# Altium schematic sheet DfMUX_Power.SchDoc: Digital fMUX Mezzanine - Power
size 513 x 386 mm; Engineer: M.Dobbs, McGill U.; Revision: 4
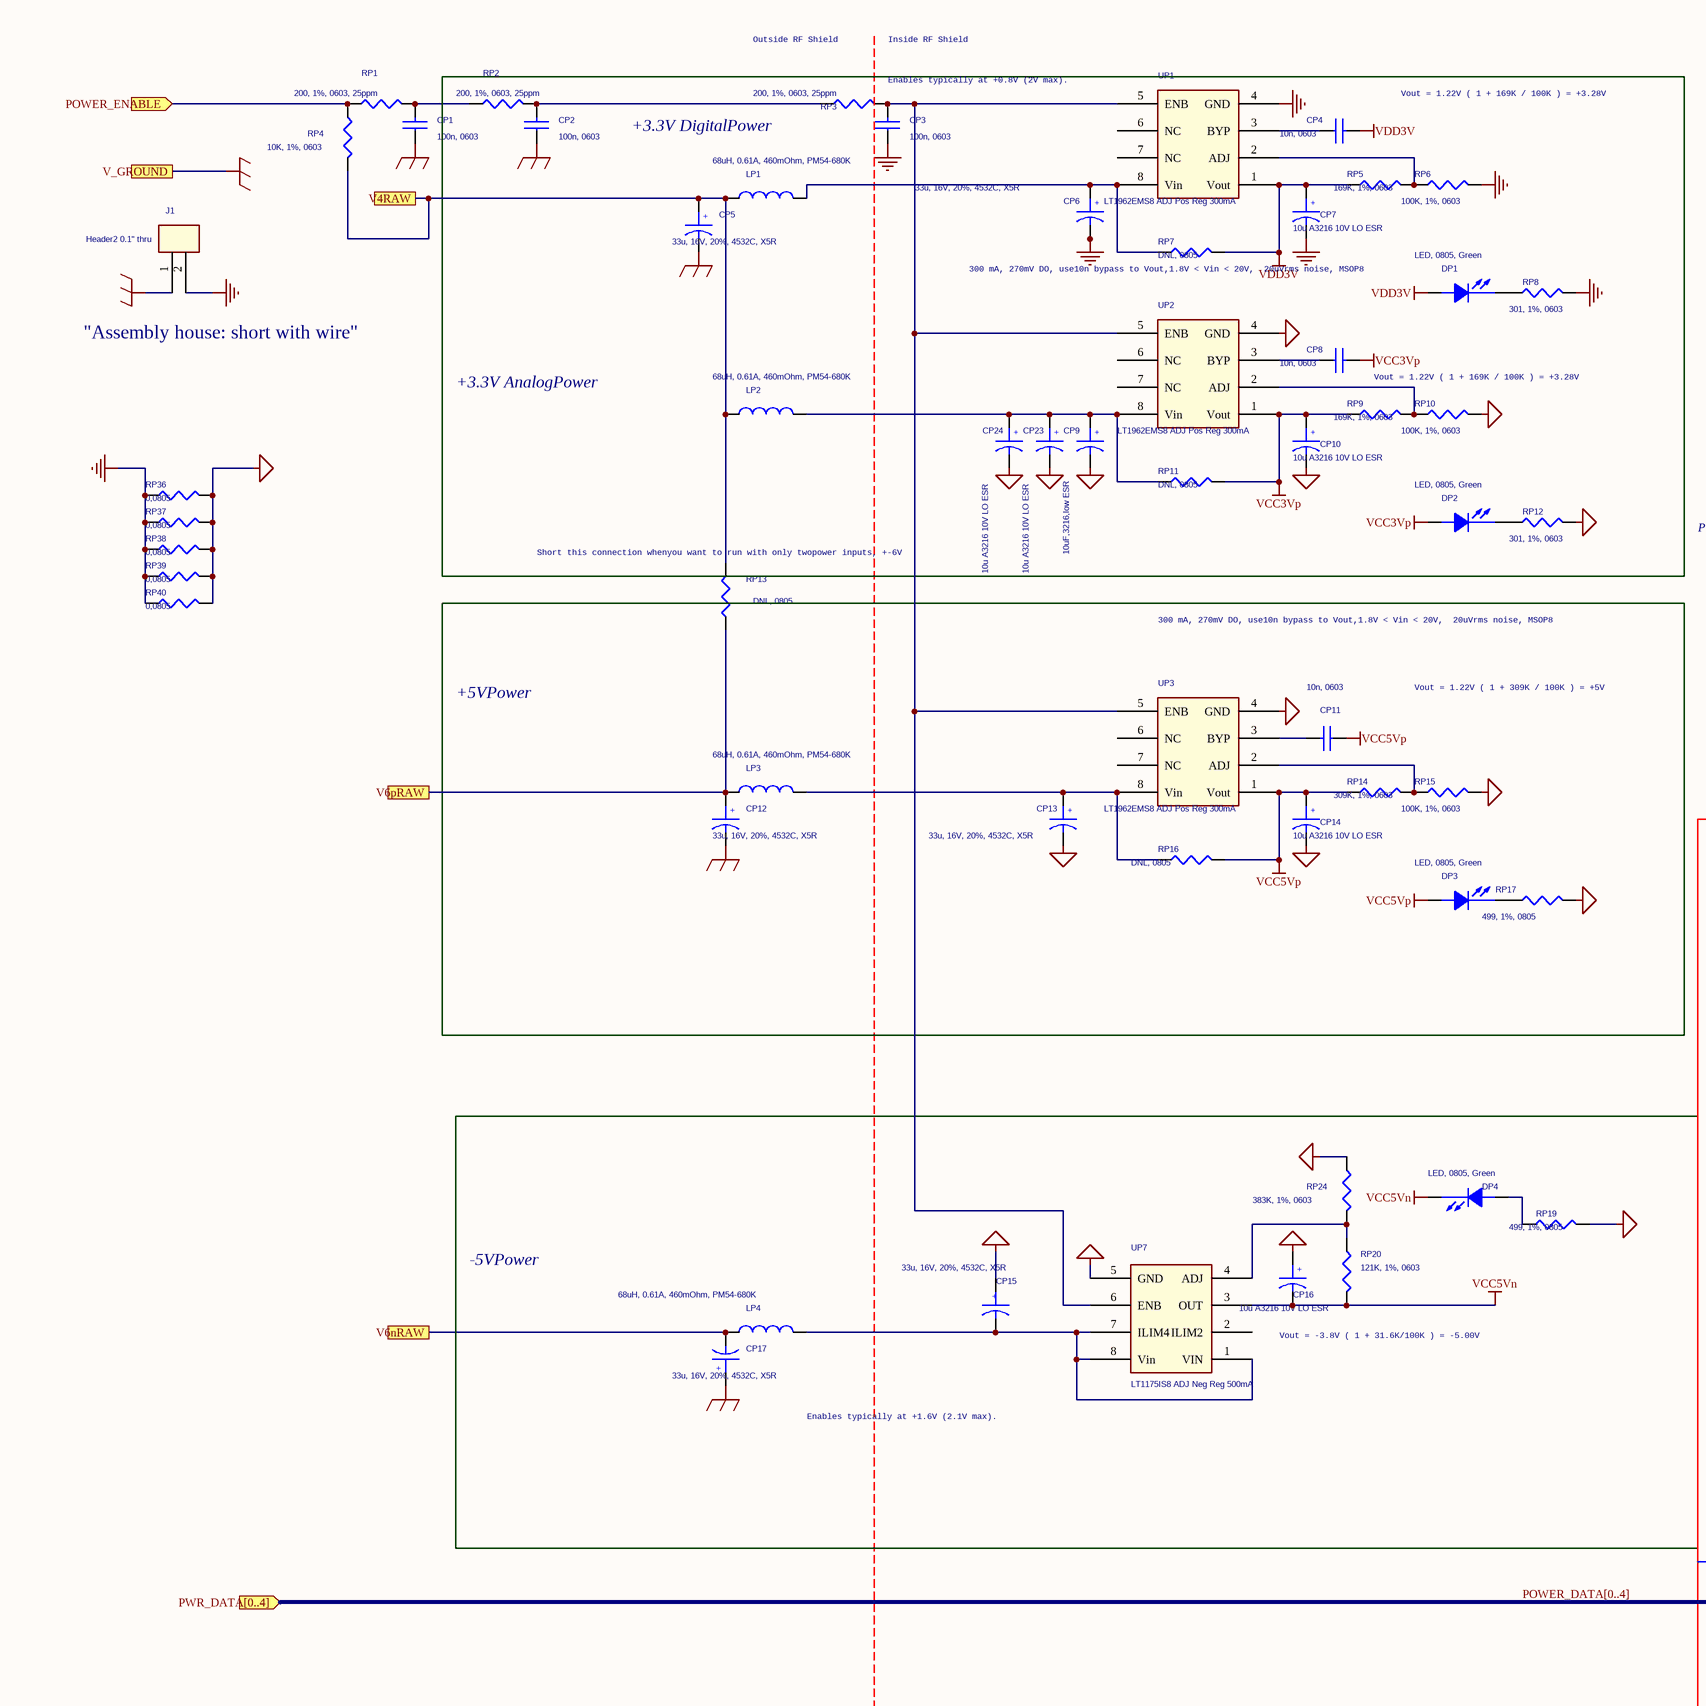
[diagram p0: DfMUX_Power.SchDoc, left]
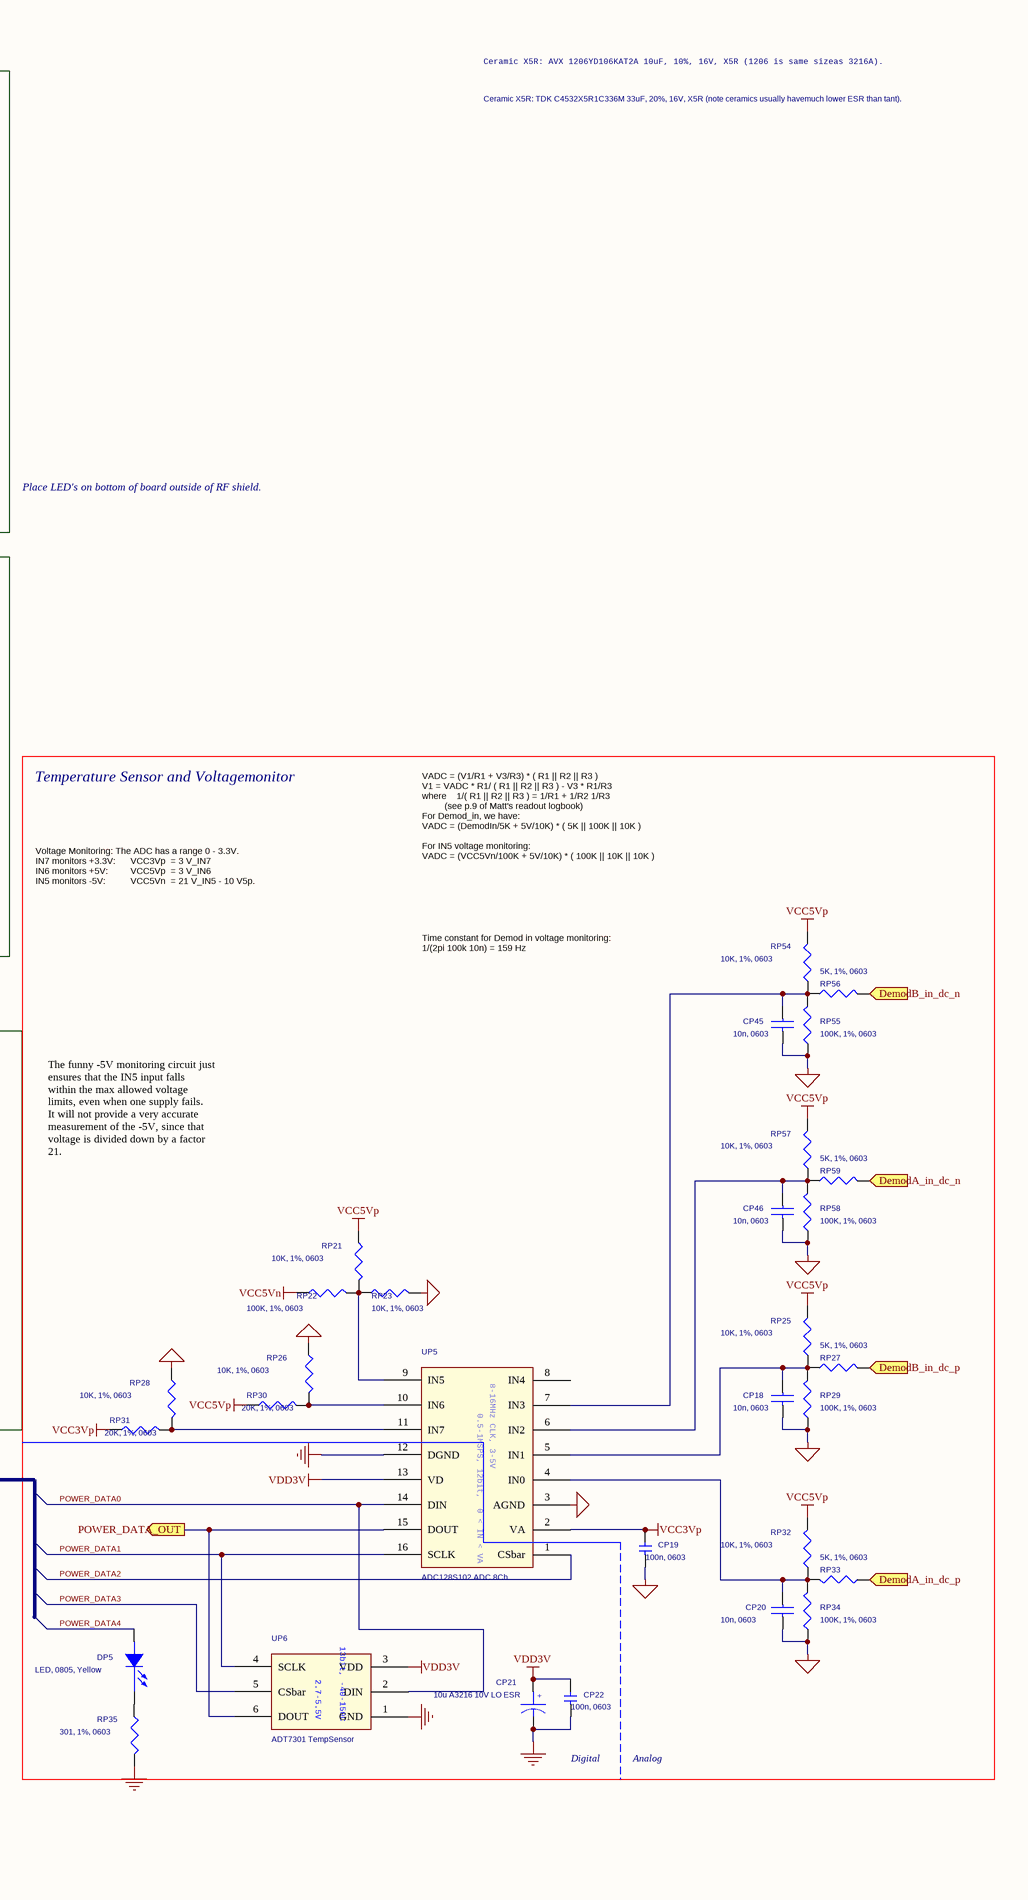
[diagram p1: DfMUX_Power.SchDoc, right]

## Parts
CP1  100n, 0603  [0603c]
CP2  100n, 0603  [0603c]
CP3  100n, 0603  [0603c]
CP4  10n, 0603  [0603c]
CP5  33u, 16V, 20%, 4532C, X5R  [TANT4532]
CP6  33u, 16V, 20%, 4532C, X5R  [TANT4532]
CP7  10u A3216 10V LO ESR  [TANTA]
CP8  10n, 0603  [0603c]
CP9  10uF,3216,low ESR  [TANTA]
CP10  10u A3216 10V LO ESR  [TANTA]
CP11  10n, 0603  [0603c]
CP12  33u, 16V, 20%, 4532C, X5R  [TANT4532]
CP13  33u, 16V, 20%, 4532C, X5R  [TANT4532]
CP14  10u A3216 10V LO ESR  [TANTA]
CP15  33u, 16V, 20%, 4532C, X5R  [TANT4532]
CP16  10u A3216 10V LO ESR  [TANTA]
CP17  33u, 16V, 20%, 4532C, X5R  [TANT4532]
CP18  10n, 0603  [0603c]
CP19  100n, 0603  [CK05]
CP20  10n, 0603  [0603c]
CP21  10u A3216 10V LO ESR  [TANTA]
CP22  100n, 0603  [CK05]
CP23  10u A3216 10V LO ESR  [TANTA]
CP24  10u A3216 10V LO ESR  [TANTA]
CP45  10n, 0603  [0603c]
CP46  10n, 0603  [0603c]
DP1  LED, 0805, Green  [0805L]
DP2  LED, 0805, Green  [0805L]
DP3  LED, 0805, Green  [0805L]
DP4  LED, 0805, Green  [0805L]
DP5  LED, 0805, Yellow  [0805L]
J1  Header2 0.1" thru  [BLKCON.100/VH/TM1SQS/W.100/2]
LP1  68uH, 0.61A, 460mOhm, PM54-680K  [L2012C]
LP2  68uH, 0.61A, 460mOhm, PM54-680K  [L2012C]
LP3  68uH, 0.61A, 460mOhm, PM54-680K  [L2012C]
LP4  68uH, 0.61A, 460mOhm, PM54-680K  [L2012C]
RP1  200, 1%, 0603, 25ppm  [0603r]
RP2  200, 1%, 0603, 25ppm  [0603r]
RP3  200, 1%, 0603, 25ppm  [0603r]
RP4  10K, 1%, 0603  [0603r]
RP5  169K, 1%, 0603  [0603r]
RP6  100K, 1%, 0603  [0603r]
RP7  DNL, 0805  [0805r]
RP8  301, 1%, 0603  [0603r]
RP9  169K, 1%, 0603  [0603r]
RP10  100K, 1%, 0603  [0603r]
RP11  DNL, 0805  [0805r]
RP12  301, 1%, 0603  [0603r]
RP13  DNL, 0805  [0805r]
RP14  309K, 1%, 0603  [0603r]
RP15  100K, 1%, 0603  [0603r]
RP16  DNL, 0805  [0805r]
RP17  499, 1%, 0805  [0805r]
RP19  499, 1%, 0805  [0805r]
RP20  121K, 1%, 0603  [0603r]
RP21  10K, 1%, 0603  [0603r]
RP22  100K, 1%, 0603  [0603r]
RP23  10K, 1%, 0603  [0603r]
RP24  383K, 1%, 0603  [0603r]
RP25  10K, 1%, 0603  [0603r]
RP26  10K, 1%, 0603  [0603r]
RP27  5K, 1%, 0603  [0603r]
RP28  10K, 1%, 0603  [0603r]
RP29  100K, 1%, 0603  [0603r]
RP30  20K, 1%, 0603  [0603r]
RP31  20K, 1%, 0603  [0603r]
RP32  10K, 1%, 0603  [0603r]
RP33  5K, 1%, 0603  [0603r]
RP34  100K, 1%, 0603  [0603r]
RP35  301, 1%, 0603  [0603r]
RP36  0,0805  [0805r]
RP37  0,0805  [0805r]
RP38  0,0805  [0805r]
RP39  0,0805  [0805r]
RP40  0,0805  [0805r]
RP54  10K, 1%, 0603  [0603r]
RP55  100K, 1%, 0603  [0603r]
RP56  5K, 1%, 0603  [0603r]
RP57  10K, 1%, 0603  [0603r]
RP58  100K, 1%, 0603  [0603r]
RP59  5K, 1%, 0603  [0603r]
UP1  LT1962EMS8 ADJ Pos Reg 300mA  [MSOP8]
UP2  LT1962EMS8 ADJ Pos Reg 300mA  [MSOP8]
UP3  LT1962EMS8 ADJ Pos Reg 300mA  [MSOP8]
UP5  ADC128S102 ADC 8Ch  [TSSOP16]
UP6  ADT7301 TempSensor  [SOT23]
UP7  LT1175IS8 ADJ Neg Reg 500mA  [MSOP8]

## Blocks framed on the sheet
+5V / Power: CP11-CP14 DP3 LP3 RP14-RP17 UP3
Temperature Sensor and Voltage / monitor: CP18-CP22 CP45 CP46 DP5 RP21-RP23 RP25-RP35 RP54-RP59 UP5 UP6
-5V / Power: CP15-CP17 DP4 LP4 RP19 RP20 RP24 UP7

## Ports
DemodA_in_dc_n, DemodA_in_dc_p, DemodB_in_dc_n, DemodB_in_dc_p, POWER_DATA_OUT, POWER_ENABLE, PWR_DATA[0..4], V4RAW, V6nRAW, V6pRAW, V_GROUND

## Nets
GND_DIG: CP3.1 CP6.2 CP7.2 CP21.2 CP22.1 J1.2 RP6.2 RP8.2 RP35.2 RP36.1 RP37.1 RP38.1 RP39.1 RP40.1 UP1.4(GND) UP5.12(DGND) UP6.1(GND)
GND_EARTH: CP1.1 CP2.1 CP5.2 CP12.2 CP17.1 J1.1 ; port V_GROUND
GND_SIGNAL: CP9.2 CP10.2 CP13.2 CP14.2 CP15.1 CP16.1 CP18.2 CP19.1 CP20.2 CP23.2 CP24.2 CP45.2 CP46.2 RP10.2 RP12.2 RP15.2 RP17.2 RP19.2 RP23.2 RP24.1 RP26.1 RP28.1 RP29.1 RP34.1 RP36.2 RP37.2 RP38.2 RP39.2 RP40.2 RP55.1 RP58.1 UP2.4(GND) UP3.4(GND) UP5.3(AGND) UP7.5(GND)
VCC3Vp: CP8.2 CP10.1 CP19.2 DP2.1(ANODE) RP9.1 RP11.2 RP31.1 UP2.1(Vout) UP5.2(VA)
VCC5Vn: CP16.2 DP4.2(CATHODE) RP20.2 RP22.1 UP7.3(OUT)
VCC5Vp: CP11.1 CP14.1 DP3.1(ANODE) RP14.1 RP16.2 RP21.1 RP25.2 RP30.1 RP32.2 RP54.2 RP57.2 UP3.1(Vout)
VDD3V: CP4.2 CP7.1 CP21.1 CP22.2 DP1.1(ANODE) RP5.1 RP7.2 UP1.1(Vout) UP5.13(VD) UP6.3(VDD)
DemodA_in_dc_n: RP59.2 ; port DemodA_in_dc_n
DemodA_in_dc_p: RP33.1 ; port DemodA_in_dc_p
DemodB_in_dc_n: RP56.2 ; port DemodB_in_dc_n
DemodB_in_dc_p: RP27.2 ; port DemodB_in_dc_p
POWER_DATA0: UP5.14(DIN) UP6.2(DIN)
POWER_DATA1: UP5.16(SCLK) UP6.4(SCLK)
POWER_DATA2: UP5.1(CSbar)
POWER_DATA3: UP6.5(CSbar)
POWER_DATA4: DP5.1(ANODE)
POWER_DATA_OUT: UP5.15(DOUT) UP6.6(DOUT) ; port POWER_DATA_OUT
POWER_ENABLE: RP1.1 RP4.1 ; port POWER_ENABLE
V4RAW: CP5.1 LP1.1 LP2.1 RP4.2 RP13.2 ; port V4RAW
V6nRAW: CP17.2 LP4.1 ; port V6nRAW
V6pRAW: CP12.1 LP3.1 RP13.1 ; port V6pRAW
NetCP1_2: CP1.2 RP1.2 RP2.1
NetCP2_2: CP2.2 RP2.2 RP3.1
NetCP3_2: CP3.2 RP3.2 UP1.5(ENB) UP2.5(ENB) UP3.5(ENB) UP7.6(ENB)
NetCP4_1: CP4.1 UP1.3(BYP)
NetCP6_1: CP6.1 LP1.2 RP7.1 UP1.8(Vin)
NetCP8_1: CP8.1 UP2.3(BYP)
NetCP9_1: CP9.1 CP23.1 CP24.1 LP2.2 RP11.1 UP2.8(Vin)
NetCP11_2: CP11.2 UP3.3(BYP)
NetCP13_1: CP13.1 LP3.2 RP16.1 UP3.8(Vin)
NetCP15_2: CP15.2 LP4.2 UP7.1(VIN) UP7.7(ILIM4) UP7.8(Vin)
NetCP18_1: CP18.1 RP25.1 RP27.1 RP29.2 UP5.5(IN1)
NetCP20_1: CP20.1 RP32.1 RP33.2 RP34.2 UP5.4(IN0)
NetCP45_1: CP45.1 RP54.1 RP55.2 RP56.1 UP5.7(IN3)
NetCP46_1: CP46.1 RP57.1 RP58.2 RP59.1 UP5.6(IN2)
NetDP1_2: DP1.2(CATHODE) RP8.1
NetDP2_2: DP2.2(CATHODE) RP12.1
NetDP3_2: DP3.2(CATHODE) RP17.1
NetDP4_1: DP4.1(ANODE) RP19.1
NetDP5_2: DP5.2(CATHODE) RP35.1
NetRP5_2: RP5.2 RP6.1 UP1.2(ADJ)
NetRP9_2: RP9.2 RP10.1 UP2.2(ADJ)
NetRP14_2: RP14.2 RP15.1 UP3.2(ADJ)
NetRP20_1: RP20.1 RP24.2 UP7.4(ADJ)
NetRP21_2: RP21.2 RP22.2 RP23.1 UP5.9(IN5)
NetRP26_2: RP26.2 RP30.2 UP5.10(IN6)
NetRP28_2: RP28.2 RP31.2 UP5.11(IN7)

Not connected (* = marked no-connect by the designer): UP1 6(NC) 7(NC); UP2 6(NC) 7(NC); UP3 6(NC) 7(NC); UP5 8(IN4); UP7 2(ILIM2)

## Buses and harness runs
bus POWER_DATA[0..4] = port PWR_DATA[0..4]

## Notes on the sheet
- Outside RF Shield
- Inside RF Shield
- +3.3V DigitalPower
- Enables typically at +0.8V (2V max).
- Vout = 1.22V ( 1 + 169K / 100K ) = +3.28V
- Ceramic X5R: TDK C4532X5R1C336M 33uF, 20%, 16V, X5R (note ceramics usually havemuch lower ESR than tant).
- Ceramic X5R: AVX 1206YD106KAT2A 10uF, 10%, 16V, X5R (1206 is same sizeas 3216A).
- (near RP7) 300 mA, 270mV DO, use10n bypass to Vout,1.8V < Vin < 20V,  20uVrms noise, MSOP8
- "Assembly house: short with wire"
- +3.3V AnalogPower
- Place LED's on bottom of board outside of RF shield.
- (near RP13) Short this connection whenyou want to run with only twopower inputs, +-6V
- 300 mA, 270mV DO, use10n bypass to Vout,1.8V < Vin < 20V,  20uVrms noise, MSOP8
- Vout = 1.22V ( 1 + 309K / 100K ) = +5V
- Voltage Monitoring: The ADC has a range 0 - 3.3V.
  IN7 monitors +3.3V:      VCC3Vp  = 3 V_IN7
  IN6 monitors +5V:         VCC5Vp  = 3 V_IN6
  IN5 monitors -5V:          VCC5Vn  = 21 V_IN5 - 10 V5p.
- (near RP54) VADC = (V1/R1 + V3/R3) * ( R1 || R2 || R3 )
  V1 = VADC * R1/ ( R1 || R2 || R3 ) - V3 * R1/R3
  where    1/( R1 || R2 || R3 ) = 1/R1 + 1/R2 1/R3
  (see p.9 of Matt's readout logbook)
  For Demod_in, we have:
  VADC = (DemodIn/5K + 5V/10K) * ( 5K || 100K || 10K )
  For IN5 voltage monitoring:
  VADC = (VCC5Vn/100K + 5V/10K) * ( 100K || 10K || 10K )
- Time constant for Demod in voltage monitoring:
  1/(2pi 100k 10n) = 159 Hz
- Vout = -3.8V ( 1 + 31.6K/100K ) = -5.00V
- The funny -5V monitoring circuit just
  ensures that the IN5 input falls
  within the max allowed voltage
  limits, even when one supply fails.
  It will not provide a very accurate
  measurement of the -5V, since that
  voltage is divided down by a factor
  21.
- Enables typically at +1.6V (2.1V max).
- Digital
- Analog

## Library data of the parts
CP1 = CAP NP: COMPFIXED: NO; COMPGROUP: 0; COMPHEIGHT: 0.000; COMPLOC: [1034.633,740.000]; COMPSIDE: TOP
CP2 = CAP NP: COMPFIXED: NO; COMPGROUP: 0; COMPHEIGHT: 0.000; COMPLOC: [1039.633,1155.000]; COMPSIDE: TOP
CP3 = CAP NP: COMPFIXED: NO; COMPGROUP: 0; COMPHEIGHT: 0.000; COMPLOC: [1372.633,1318.000]; COMPSIDE: BOT
CP4 = CAP NP: COMPFIXED: NO; COMPGROUP: 0; COMPHEIGHT: 0.000; COMPLOC: [1429.633,1320.000]; COMPROT: 180; COMPSIDE: BOT
CP5 = CAP_POL: COMPFIXED: NO; COMPGROUP: 0; COMPHEIGHT: 0.000; COMPLOC: [539.633,1474.367]; COMPSIDE: TOP
CP6 = CAP_POL: COMPFIXED: NO; COMPGROUP: 0; COMPHEIGHT: 0.000; COMPLOC: [1309.633,1595.000]; COMPROT: 90; COMPSIDE: TOP
CP7 = CAP_POL: COMPFIXED: NO; COMPGROUP: 0; COMPHEIGHT: 0.000; COMPLOC: [1523.633,1584.000]; COMPROT: 90; COMPSIDE: TOP
CP8 = CAP NP: COMPFIXED: NO; COMPGROUP: 0; COMPHEIGHT: 0.000; COMPLOC: [2397.633,1480.000]; COMPROT: 90; COMPSIDE: TOP
CP9 = CAP_POL: COMPFIXED: NO; COMPGROUP: 0; COMPHEIGHT: 0.000; COMPLOC: [2205.000,1380.000]; COMPROT: 90; COMPSIDE: BOT; FPLIST: TANT4532
CP10 = CAP_POL: COMPFIXED: NO; COMPGROUP: 0; COMPHEIGHT: 0.000; COMPLOC: [2347.633,1365.000]; COMPSIDE: TOP
CP11 = CAP NP: COMPFIXED: NO; COMPGROUP: 0; COMPHEIGHT: 0.000; COMPLOC: [2267.633,3385.000]; COMPROT: 90; COMPSIDE: BOT
CP12 = CAP_POL: COMPFIXED: NO; COMPGROUP: 0; COMPHEIGHT: 0.000; COMPLOC: [689.633,3195.000]; COMPROT: 270; COMPSIDE: TOP
CP13 = CAP_POL: COMPFIXED: NO; COMPGROUP: 0; COMPHEIGHT: 0.000; COMPLOC: [1619.633,3500.000]; COMPSIDE: TOP
CP14 = CAP_POL: COMPFIXED: NO; COMPGROUP: 0; COMPHEIGHT: 0.000; COMPLOC: [2192.633,3445.000]; COMPROT: 180; COMPSIDE: BOT
CP15 = CAP_POL: COMPFIXED: NO; COMPGROUP: 0; COMPHEIGHT: 0.000; COMPLOC: [2204.633,120.000]; COMPROT: 180; COMPSIDE: TOP
CP16 = CAP_POL: COMPFIXED: NO; COMPGROUP: 0; COMPHEIGHT: 0.000; COMPLOC: [2319.633,355.000]; COMPROT: 180; COMPSIDE: BOT
CP17 = CAP_POL: COMPFIXED: NO; COMPGROUP: 0; COMPHEIGHT: 0.000; COMPLOC: [709.633,385.000]; COMPROT: 180; COMPSIDE: TOP
CP18 = CAP NP: COMPFIXED: NO; COMPGROUP: 0; COMPHEIGHT: 0.000; COMPLOC: [3832.633,1939.367]; COMPROT: 90; COMPSIDE: TOP
CP19 = C: PSpiceTemplate: C^@REFDES %1 %2 ?TOLERANCE|C^@REFDES| @VALUE ?IC/IC=@IC/ ?TOLERANCE|\n.model C^@REFDES CAP C=1 DEV=@TOLERANCE%|; COMPFIXED: NO; COMPGROUP: 0; COMPHEIGHT: 0.000; COMPLOC: [1827.633,1264.367]; COMPSIDE: BOT
CP20 = CAP NP: COMPFIXED: NO; COMPGROUP: 0; COMPHEIGHT: 0.000; COMPLOC: [3837.633,1434.367]; COMPROT: 90; COMPSIDE: TOP
CP21 = CAPACITOR POL: COMPFIXED: NO; COMPGROUP: 0; COMPHEIGHT: 0.000; COMPLOC: [1897.633,1559.367]; COMPROT: 180; COMPSIDE: TOP
CP22 = C: PSpiceTemplate: C^@REFDES %1 %2 ?TOLERANCE|C^@REFDES| @VALUE ?IC/IC=@IC/ ?TOLERANCE|\n.model C^@REFDES CAP C=1 DEV=@TOLERANCE%|; COMPFIXED: NO; COMPGROUP: 0; COMPHEIGHT: 0.000; COMPLOC: [1657.633,1459.367]; COMPSIDE: TOP
CP23 CP24 = CAP_POL
CP45 CP46 = CAP NP
DP1 = LED: COMPFIXED: NO; COMPGROUP: 0; COMPHEIGHT: 0.000; COMPLOC: [1354.633,2215.000]; COMPROT: 270; COMPSIDE: BOT
DP2 = LED: COMPFIXED: NO; COMPGROUP: 0; COMPHEIGHT: 0.000; COMPLOC: [2401.633,2092.000]; COMPROT: 90; COMPSIDE: BOT
DP3 = LED: COMPFIXED: NO; COMPGROUP: 0; COMPHEIGHT: 0.000; COMPLOC: [2144.633,3525.000]; COMPROT: 180; COMPSIDE: BOT
DP4 = LED: COMPFIXED: NO; COMPGROUP: 0; COMPHEIGHT: 0.000; COMPLOC: [2839.633,145.000]; COMPSIDE: BOT
DP5 = LED: COMPFIXED: NO; COMPGROUP: 0; COMPHEIGHT: 0.000; COMPLOC: [1264.633,393.367]; COMPROT: 90; COMPSIDE: BOT
J1 = CON2: COMPFIXED: NO; COMPGROUP: 0; COMPHEIGHT: 0.000; COMPLOC: [979.633,105.000]; COMPSIDE: TOP; FPLIST: HEADER_AMP146128
LP1 = L: PSpiceTemplate: L^@REFDES %1 %2 ?TOLERANCE|L^@REFDES| @VALUE ?IC/IC=@IC/ ?TOLERANCE|\n.model l^@REFDES IND L=1 DEV=@TOLERANCE%|; COMPFIXED: NO; COMPGROUP: 0; COMPHEIGHT: 0.000; COMPLOC: [549.633,1744.367]; COMPSIDE: TOP
LP2 = L: PSpiceTemplate: L^@REFDES %1 %2 ?TOLERANCE|L^@REFDES| @VALUE ?IC/IC=@IC/ ?TOLERANCE|\n.model l^@REFDES IND L=1 DEV=@TOLERANCE%|; COMPFIXED: NO; COMPGROUP: 0; COMPHEIGHT: 0.000; COMPLOC: [549.633,1229.367]; COMPSIDE: TOP
LP3 = L: PSpiceTemplate: L^@REFDES %1 %2 ?TOLERANCE|L^@REFDES| @VALUE ?IC/IC=@IC/ ?TOLERANCE|\n.model l^@REFDES IND L=1 DEV=@TOLERANCE%|; COMPFIXED: NO; COMPGROUP: 0; COMPHEIGHT: 0.000; COMPLOC: [559.633,3390.000]; COMPSIDE: TOP
LP4 = L: PSpiceTemplate: L^@REFDES %1 %2 ?TOLERANCE|L^@REFDES| @VALUE ?IC/IC=@IC/ ?TOLERANCE|\n.model l^@REFDES IND L=1 DEV=@TOLERANCE%|; COMPFIXED: NO; COMPGROUP: 0; COMPHEIGHT: 0.000; COMPLOC: [514.633,175.000]; COMPSIDE: TOP
RP1 = R_Dup1: COMPFIXED: NO; COMPGROUP: 0; COMPHEIGHT: 0.000; COMPLOC: [1074.633,625.000]; COMPROT: 90; COMPSIDE: TOP
RP2 = R_Dup1: COMPFIXED: NO; COMPGROUP: 0; COMPHEIGHT: 0.000; COMPLOC: [1089.633,855.000]; COMPROT: 90; COMPSIDE: TOP
RP3 = R_Dup1: COMPFIXED: NO; COMPGROUP: 0; COMPHEIGHT: 0.000; COMPLOC: [1094.633,1210.000]; COMPROT: 90; COMPSIDE: TOP
RP4 = R_Dup1: COMPFIXED: NO; COMPGROUP: 0; COMPHEIGHT: 0.000; COMPLOC: [449.633,476.000]; COMPROT: 270; COMPSIDE: TOP
RP5 = R: COMPFIXED: NO; COMPGROUP: 0; COMPHEIGHT: 0.000; COMPLOC: [1554.633,1540.000]; COMPROT: 90; COMPSIDE: BOT
RP6 = R: COMPFIXED: NO; COMPGROUP: 0; COMPHEIGHT: 0.000; COMPLOC: [1554.633,1445.000]; COMPROT: 90; COMPSIDE: BOT
RP7 = R_Dup1: COMPFIXED: NO; COMPGROUP: 0; COMPHEIGHT: 0.000; COMPLOC: [1364.633,1505.000]; COMPROT: 180; COMPSIDE: BOT
RP8 = R_Dup1: COMPFIXED: NO; COMPGROUP: 0; COMPHEIGHT: 0.000; COMPLOC: [1356.633,2377.000]; COMPROT: 270; COMPSIDE: BOT
RP9 = R: COMPFIXED: NO; COMPGROUP: 0; COMPHEIGHT: 0.000; COMPLOC: [2452.633,1535.000]; COMPROT: 270; COMPSIDE: TOP
RP10 = R: COMPFIXED: NO; COMPGROUP: 0; COMPHEIGHT: 0.000; COMPLOC: [2397.633,1425.000]; COMPSIDE: TOP
RP11 = R_Dup1: COMPFIXED: NO; COMPGROUP: 0; COMPHEIGHT: 0.000; COMPLOC: [2192.633,1365.000]; COMPSIDE: TOP
RP12 = R_Dup1: COMPFIXED: NO; COMPGROUP: 0; COMPHEIGHT: 0.000; COMPLOC: [2402.633,1943.000]; COMPROT: 90; COMPSIDE: BOT
RP13 = R_Dup1: COMPFIXED: NO; COMPGROUP: 0; COMPHEIGHT: 0.000; COMPLOC: [564.633,3225.000]; COMPROT: 270; COMPSIDE: TOP
RP14 = R: COMPFIXED: NO; COMPGROUP: 0; COMPHEIGHT: 0.000; COMPLOC: [2324.633,3383.000]; COMPROT: 90; COMPSIDE: BOT
RP15 = R: COMPFIXED: NO; COMPGROUP: 0; COMPHEIGHT: 0.000; COMPLOC: [2379.633,3327.000]; COMPROT: 270; COMPSIDE: BOT
RP16 = R_Dup1: COMPFIXED: NO; COMPGROUP: 0; COMPHEIGHT: 0.000; COMPLOC: [2002.633,3445.000]; COMPROT: 180; COMPSIDE: BOT
RP17 = R_Dup1: COMPFIXED: NO; COMPGROUP: 0; COMPHEIGHT: 0.000; COMPLOC: [2294.633,3525.000]; COMPROT: 180; COMPSIDE: BOT
RP19 = R_Dup1: COMPFIXED: NO; COMPGROUP: 0; COMPHEIGHT: 0.000; COMPLOC: [2909.633,145.000]; COMPROT: 180; COMPSIDE: BOT
RP20 = R: COMPFIXED: NO; COMPGROUP: 0; COMPHEIGHT: 0.000; COMPLOC: [2514.633,314.000]; COMPROT: 270; COMPSIDE: BOT
RP21 = R_Dup1: COMPFIXED: NO; COMPGROUP: 0; COMPHEIGHT: 0.000; COMPLOC: [2032.633,1370.000]; COMPROT: 180; COMPSIDE: TOP
RP22 = R_Dup1: COMPFIXED: NO; COMPGROUP: 0; COMPHEIGHT: 0.000; COMPLOC: [2032.633,1429.367]; COMPROT: 180; COMPSIDE: TOP
RP23 = R_Dup1: COMPFIXED: NO; COMPGROUP: 0; COMPHEIGHT: 0.000; COMPLOC: [1977.633,1489.367]; COMPSIDE: TOP
RP24 = R: COMPFIXED: NO; COMPGROUP: 0; COMPHEIGHT: 0.000; COMPLOC: [2569.633,371.000]; COMPROT: 90; COMPSIDE: BOT
RP25 = R_Dup1: COMPFIXED: NO; COMPGROUP: 0; COMPHEIGHT: 0.000; COMPLOC: [3697.633,1889.367]; COMPROT: 180; COMPSIDE: TOP
RP26 = R_Dup1: COMPFIXED: NO; COMPGROUP: 0; COMPHEIGHT: 0.000; COMPLOC: [2095.633,1251.367]; COMPROT: 90; COMPSIDE: TOP
RP27 = R_Dup1: COMPFIXED: NO; COMPGROUP: 0; COMPHEIGHT: 0.000; COMPLOC: [3775.633,1936.367]; COMPROT: 90; COMPSIDE: TOP
RP28 = R_Dup1: COMPFIXED: NO; COMPGROUP: 0; COMPHEIGHT: 0.000; COMPLOC: [2037.633,1249.367]; COMPROT: 90; COMPSIDE: TOP
RP29 = R_Dup1: COMPFIXED: NO; COMPGROUP: 0; COMPHEIGHT: 0.000; COMPLOC: [3793.633,1889.367]; COMPROT: 180; COMPSIDE: TOP
RP30 = R_Dup1: COMPFIXED: NO; COMPGROUP: 0; COMPHEIGHT: 0.000; COMPLOC: [2150.633,1250.367]; COMPROT: 90; COMPSIDE: TOP
RP31 = R_Dup1: COMPFIXED: NO; COMPGROUP: 0; COMPHEIGHT: 0.000; COMPLOC: [1977.633,1249.367]; COMPROT: 90; COMPSIDE: TOP
RP32 = R_Dup1: COMPFIXED: NO; COMPGROUP: 0; COMPHEIGHT: 0.000; COMPLOC: [3697.633,1389.367]; COMPROT: 180; COMPSIDE: TOP
RP33 = R_Dup1: COMPFIXED: NO; COMPGROUP: 0; COMPHEIGHT: 0.000; COMPLOC: [3782.633,1489.367]; COMPROT: 270; COMPSIDE: TOP
RP34 = R_Dup1: COMPFIXED: NO; COMPGROUP: 0; COMPHEIGHT: 0.000; COMPLOC: [3797.633,1389.367]; COMPROT: 180; COMPSIDE: TOP
RP35 = R_Dup1: COMPFIXED: NO; COMPGROUP: 0; COMPHEIGHT: 0.000; COMPLOC: [1264.633,260.000]; COMPROT: 90; COMPSIDE: BOT
RP36 = R_Dup1: COMPFIXED: NO; COMPGROUP: 0; COMPHEIGHT: 0.000; COMPLOC: [1724.633,2905.000]; COMPROT: 180; COMPSIDE: BOT
RP37 = R_Dup1: COMPFIXED: NO; COMPGROUP: 0; COMPHEIGHT: 0.000; COMPLOC: [1710.633,2445.000]; COMPROT: 180; COMPSIDE: BOT
RP38 = R_Dup1: COMPFIXED: NO; COMPGROUP: 0; COMPHEIGHT: 0.000; COMPLOC: [1854.633,1908.000]; COMPROT: 180; COMPSIDE: BOT
RP39 = R_Dup1: COMPFIXED: NO; COMPGROUP: 0; COMPHEIGHT: 0.000; COMPLOC: [1730.633,830.000]; COMPROT: 180; COMPSIDE: BOT
RP40 = R_Dup1: COMPFIXED: NO; COMPGROUP: 0; COMPHEIGHT: 0.000; COMPLOC: [1731.633,384.000]; COMPROT: 180; COMPSIDE: BOT
RP54-RP59 = R_Dup1
UP1 = LT1962EMS8_0_Dup1: COMPFIXED: NO; COMPGROUP: 0; COMPHEIGHT: 0.000; COMPLOC: [1489.633,1445.000]; COMPROT: 90; COMPSIDE: BOT
UP2 = LT1962EMS8_0_Dup1: COMPFIXED: NO; COMPGROUP: 0; COMPHEIGHT: 0.000; COMPLOC: [2332.633,1420.000]; COMPROT: 90; COMPSIDE: TOP
UP3 = LT1962EMS8_0_Dup1: COMPFIXED: NO; COMPGROUP: 0; COMPHEIGHT: 0.000; COMPLOC: [2192.633,3385.000]; COMPROT: 90; COMPSIDE: BOT
UP5 = ADC128S102 ADC 8Ch: COMPFIXED: NO; COMPGROUP: 0; COMPHEIGHT: 0.000; COMPLOC: [1755.933,1241.800]; COMPSIDE: TOP
UP6 = ADT7301 TempSensor: COMPFIXED: NO; COMPGROUP: 0; COMPHEIGHT: 0.000; COMPLOC: [1712.633,1314.367]; COMPROT: 90; COMPSIDE: TOP
UP7 = LT1962EMS8_5: COMPFIXED: NO; COMPGROUP: 0; COMPHEIGHT: 0.000; COMPLOC: [2454.633,100.000]; COMPROT: 270; COMPSIDE: BOT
